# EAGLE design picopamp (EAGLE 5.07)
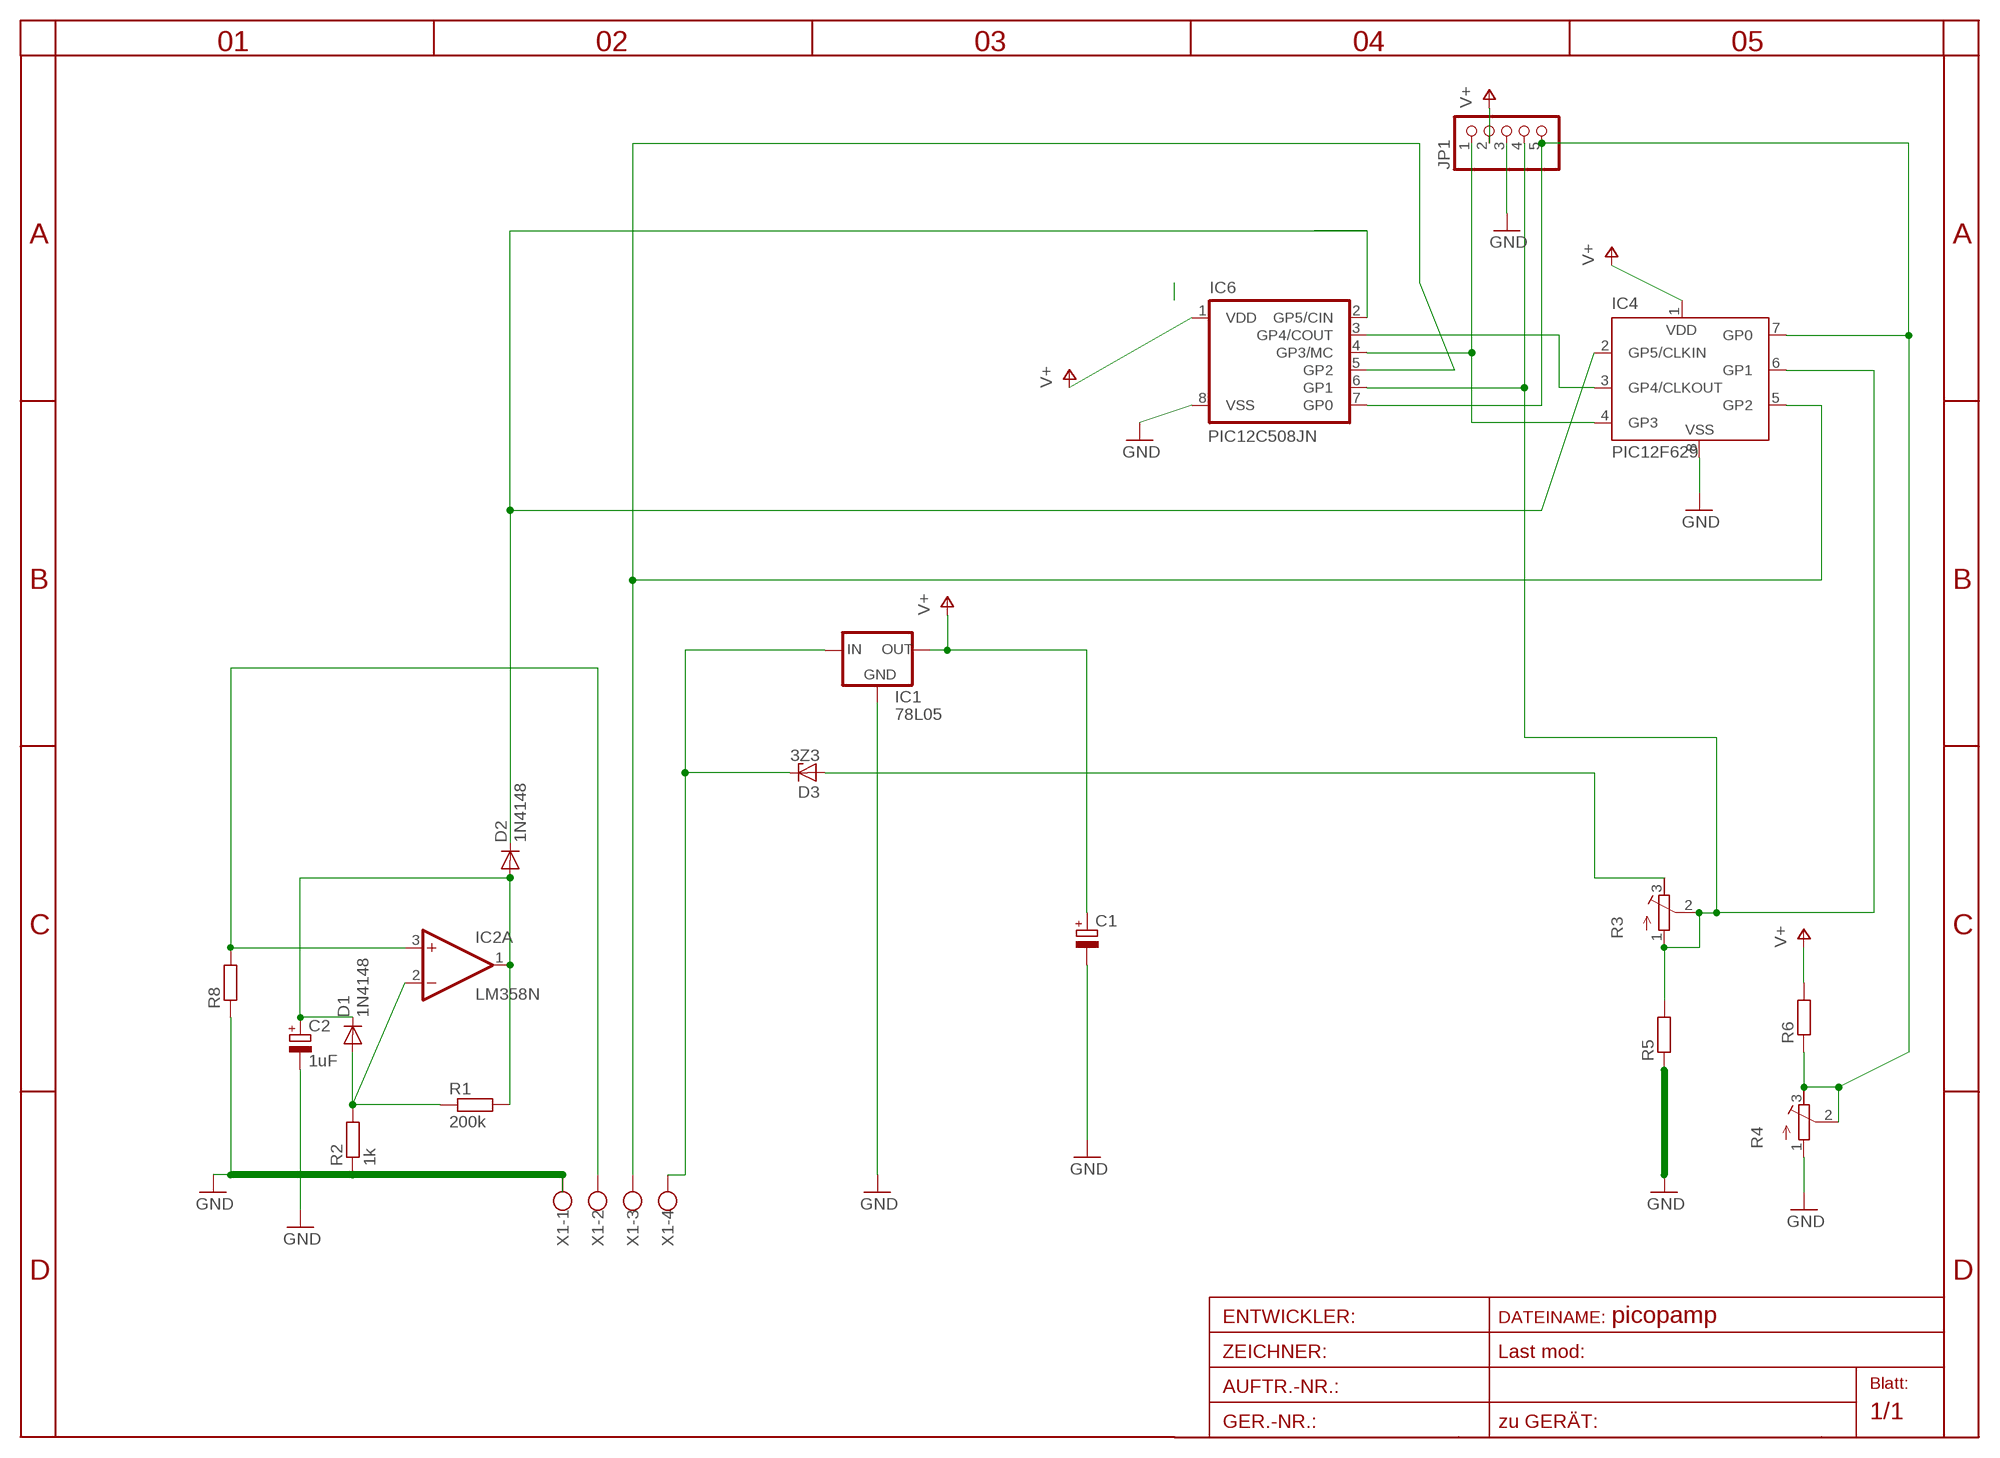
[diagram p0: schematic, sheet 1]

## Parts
C1  CPOL-EUE5-10.5  [E5-10,5]
C2  1uF  CPOL-EUE5-10.5  [E5-10,5]
D1  1N4148  [DO35-10]
D2  1N4148  [DO35-10]
D3  3Z3  1N4728  [DO41Z10]
IC1  78L05  78LXX  [78LXX]
IC2  LM358N  [DIL08]
IC4  PIC12F629  [DFN-S]
IC6  PIC12C508JN  [DIL8]
JP1  PINHD-1X5  [1X05]
R1  200k  R-EU_0207/10  [0207/10]
R2  1k  R-EU_0207/10  [0207/10]
R3  R-TRIMM3339P  [RTRIM3339P]
R4  R-TRIMM3339P  [RTRIM3339P]
R5  R-EU_0204/7  [0204/7]
R6  R-EU_0204/7  [0204/7]
R8  R-EU_0613/15  [P0613/15]
X1  W237-4  [W237-4]

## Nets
GND: C1.- C2.- IC1.GND IC4.8(VSS) IC6.8(VSS) JP1.3 R2.1 R4.1(E) R5.1 R8.1 X1.1
N$1: D2.C IC4.2(GP5/CLKIN) IC6.2(GP5/CIN)
N$2: D1.A IC2.2(A:-IN) R1.1 R2.2
N$3: D3.A R3.3(A)
N$4: IC4.6(GP1) IC6.6(GP1) JP1.4 R3.1(E) R3.2(S) R5.2
N$5: IC4.4(GP3) IC6.4(GP3/MC) JP1.1
N$6: IC4.7(GP0) IC6.7(GP0) JP1.5 R4.2(S) R4.3(A) R6.1
N$8: IC4.5(GP2) IC6.5(GP2) X1.3
N$9: IC4.3(GP4/CLKOUT) IC6.3(GP4/COUT)
N$10: IC2.3(A:+IN) R8.2 X1.2
N$12: D3.C IC1.IN X1.4
N$18: C2.+ D1.C D2.A IC2.1(A:OUT) R1.2
V+: C1.+ IC1.OUT IC4.1(VDD) IC6.1(VDD) JP1.2 R6.2
Unconnected: IC2.5(B:+IN) IC2.6(B:-IN) IC2.7(B:OUT)

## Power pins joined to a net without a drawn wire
V+: IC2.8(P:V+)
V-: IC2.4(P:V-)

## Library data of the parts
C1 C2 = rcl:CPOL-EU: POLARIZED CAPACITOR, European symbol
D1 D2 = diode:1N4148: DIODE
D3 = diode:1N4728: Z DIODE
IC1 = v-reg:78LXX: VOLTAGE REGULATOR
IC2 = linear:LM358: OP AMP also LM158; LM258; LM2904 Source: http://cache.national.com/ds/LM/LM158.pdf
IC4 = microchip:PIC12F6*: Data Sheet 8-Pin FLASH-Based 8-Bit CMOS Microcontrollers Source: http://www.microchip.com .. 41190c.pdf
IC6 = microchip:PIC12C*?: MICROCONTROLLER
JP1 = pinhead:PINHD-1X5: PIN HEADER
R1 R2 R5 R6 R8 = rcl:R-EU_: RESISTOR, European symbol
R3 R4 = rcl:R-TRIMM: Trimm resistor
X1 = con-wago-500:W237-4: WAGO SCREW CLAMP

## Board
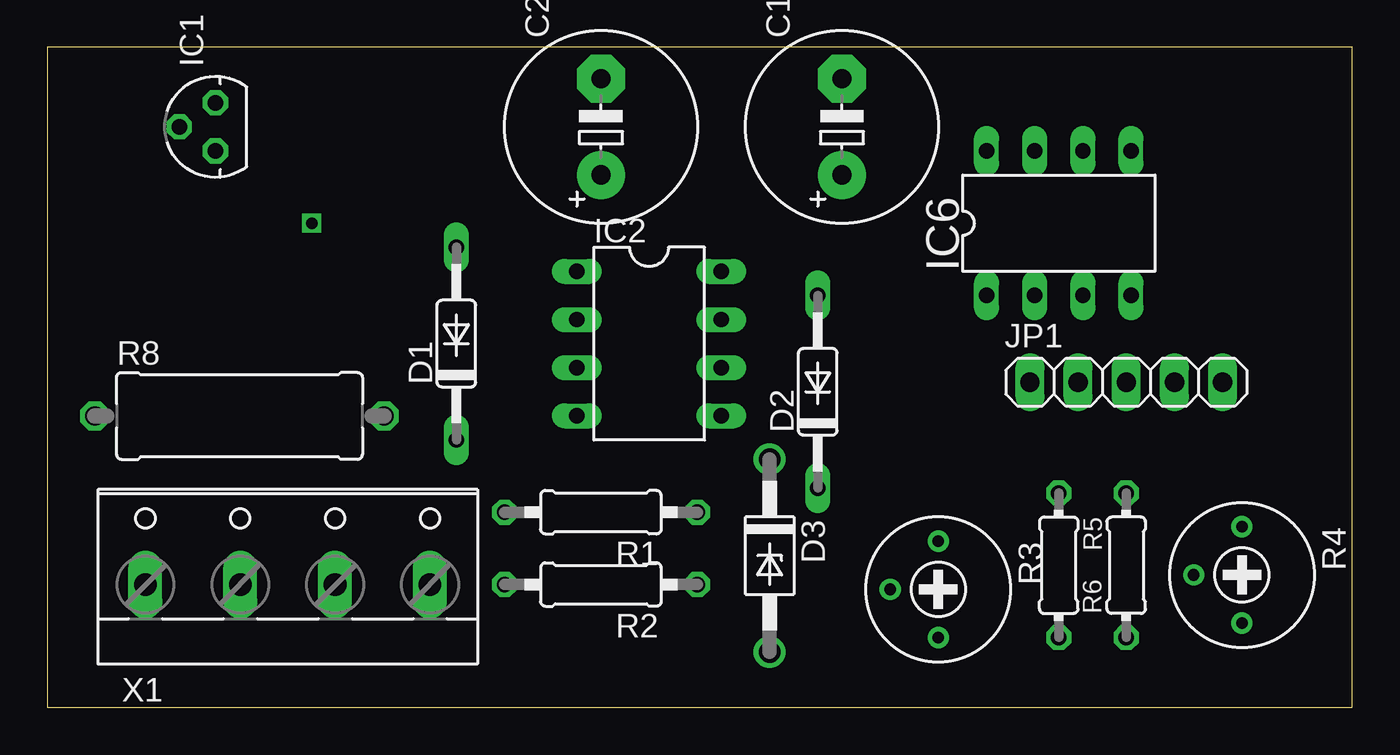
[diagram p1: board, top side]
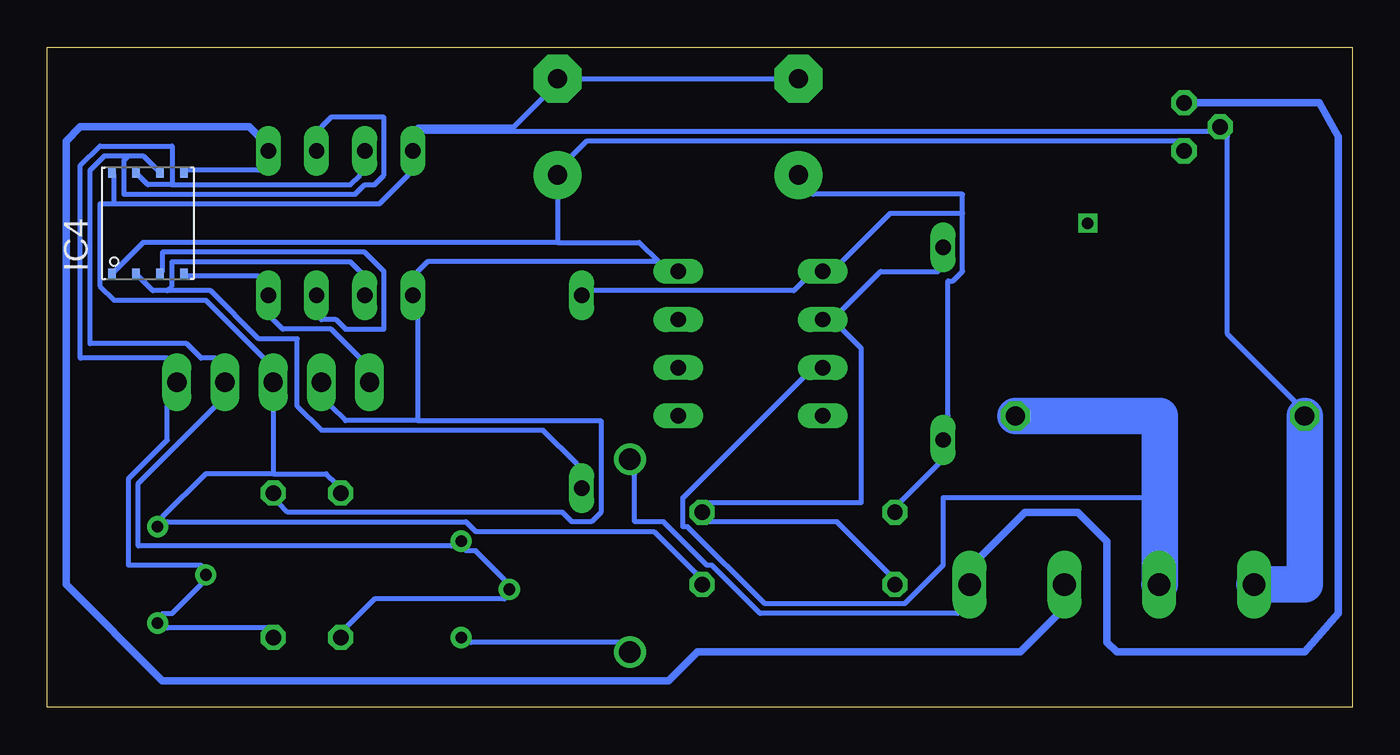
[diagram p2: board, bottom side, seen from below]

Size 68.76 x 34.79 mm. Coordinates in mm from the lower left corner, seen from the top.
Outline: 0,0 68.76,0 68.76,34.79 0,34.79 0,0
Copper layers (1*16): Top 0.035mm / dielectric 1.5mm / Bottom 0.035mm
Design rules "default": minimum track width 10mil, minimum drill 24mil, track to track 8mil, track to pad 8mil, pad to pad 8mil, via to via 8mil, smd to smd 8mil, copper to edge 40mil, drill to drill 8mil, minimum pad ring 10mil, minimum via ring 8mil, stop-mask expansion 4mil, vias tented up to drill 0mil, thermal gap 10mil
tRestrict: area 21.6,2.7 to 45.7,35.7; area 2.5,1.4 to 22.8,17.9; area 1.2,21.7 to 19,28.1; area 19,16.6 to 24.1,28.1; area 10.1,28.1 to 16.5,35.7; area 54.6,17.9 to 67.3,26.8; area 53.3,9 to 62.2,14.1; area 63.5,26.8 to 76.2,31.9; area 60.9,2.7 to 74.9,9; area 43.1,5.2 to 57.1,10.3; area 63.5,10.3 to 71.1,15.4; area 36.8,24.3 to 48.2,34.4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

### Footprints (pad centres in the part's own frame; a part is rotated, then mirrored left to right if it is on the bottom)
E5-10,5 = drill 1.016 pad 2.54 round: + -2.54,0 | drill 1.016 pad 2.54 octagon: - 2.54,0
DO35-10 = drill 0.813 long: A 5.08,0; C -5.08,0
DO41Z10 = drill 1.118 round: A 5.08,0; C -5.08,0
78LXX = drill 0.813 octagon: GND 0,1.905; IN 1.27,0; OUT -1.27,0
DIL08 = drill 0.813 long: 1 -3.81,-3.81; 2 -1.27,-3.81; 3 1.27,-3.81; 4 3.81,-3.81; 5 3.81,3.81; 6 1.27,3.81; 7 -1.27,3.81; 8 -3.81,3.81
DFN-S = smd 0.6 x 0.4: 1 -2.69,1.905; 2 -2.69,0.635; 3 -2.69,-0.635; 4 -2.69,-1.905; 5 2.69,-1.905; 6 2.69,-0.635; 7 2.69,0.635; 8 2.69,1.905
DIL8 = drill 0.813 long: 1 -3.81,-3.81; 2 -1.27,-3.81; 3 1.27,-3.81; 4 3.81,-3.81; 5 3.81,3.81; 6 1.27,3.81; 7 -1.27,3.81; 8 -3.81,3.81
1X05 = drill 1.016 long: 1 -5.08,0; 2 -2.54,0; 3 0,0; 4 2.54,0; 5 5.08,0
0207/10 = drill 0.813 octagon: 1 -5.08,0; 2 5.08,0
RTRIM3339P = drill 0.61 round: 1 -2.54,0; 2 0,-2.54; 3 2.54,0
0204/7 = drill 0.813 octagon: 1 -3.81,0; 2 3.81,0
P0613/15 = drill 1.016 octagon: 1 -7.62,0; 2 7.62,0
W237-4 = drill 1.194 long: 1 -7.5,-1.27; 2 -2.5,-1.27; 3 2.5,-1.27; 4 7.5,-1.27

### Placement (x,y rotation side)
C1  41.87,30.6 90 top
C2  29.17,30.6 90 top
D1  21.55,19.17 90 top
D2  40.6,16.63 90 top
D3  38.06,8 270 top
IC1  8.85,30.6 90 top
IC2  31.71,19.17 270 top
IC4  63.46,25.52 90 bottom
IC6  53.3,25.52 0 top
JP1  56.86,17.14 0 top
R1  29.17,10.28 180 top
R2  29.17,6.47 180 top
R3  46.95,6.22 270 top
R4  62.95,6.98 270 top
R5  53.3,7.49 270 top
R6  56.86,7.49 90 top
R8  10.12,15.36 0 top
X1  12.66,7.74 0 top

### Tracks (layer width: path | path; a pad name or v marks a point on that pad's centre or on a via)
GND
  Bottom 0.254: 56.86,12.31 54.06,12.31 53.56,11.81 R5.1 | 56.86,12.31 60.41,12.31 62.7,10.03 R4.1 62.45,9.77 46.7,9.77 46.19,9.27 36.79,9.27 34.51,6.98 R2.1 | 56.86,12.31 JP1.3 57.37,18.41 60.41,21.46 65.24,21.46 66,22.22 66,26.54 65.24,26.54 | C2.- C1.- 42.63,32.13 44.16,30.6 49.24,30.6 IC6.8 | 65.24,26.54 65.24,28.06 IC4.8 | 65.24,26.54 51.27,26.54 49.75,28.06 IC6.8 | IC6.8 48.98,30.35 7.58,30.35 IC1.GND 6.57,30.09 6.57,19.68 3.01,16.12 R8.1
  Bottom 1.93: X1.1 2.5,6.47 R8.1
N$1
  Bottom 0.254: 62.45,21.97 63.21,21.97 63.97,22.73 IC4.2 | 62.45,21.97 62.19,22.22 62.19,23.49 52.79,23.49 52.29,22.98 IC6.2 | 62.45,21.97 60.16,21.97 57.62,19.43 55.59,19.43 55.59,15.87 54.32,14.6 42.63,14.6 40.86,12.82 D2.C
N$2
  Bottom 0.254: D1.A 21.81,22.98 24.85,22.98 26.89,20.95 IC2.2 26.89,19.93 25.87,18.92 25.87,10.79 34,10.79 R1.1 34,9.77 27.14,9.77 24.35,6.98 R2.2
N$3
  Bottom 0.254: R3.3 46.44,3.42 38.57,3.42 D3.A
N$4
  Bottom 0.254: 64.48,29.08 63.72,29.08 62.95,28.32 IC4.6 | 64.48,29.08 64.73,28.82 64.73,27.05 52.54,27.05 52.03,27.55 51.52,27.55 51.02,28.06 51.02,31.11 53.81,31.11 54.32,30.6 IC6.6 | R5.2 53.05,4.19 51.52,5.71 44.67,5.71 R3.2 44.67,6.73 46.19,8.25 46.7,8.25 R3.1 47.46,8.5 63.97,8.5 63.97,11.81 59.91,15.87 JP1.4 59.91,18.41 60.67,18.41 61.43,19.17 66.51,19.17 66.51,28.32 65.75,29.08 64.48,29.08
N$5
  Bottom 0.254: IC4.4 61.43,22.73 57.62,22.73 IC6.4 56.86,20.44 56.35,19.93 53.81,19.93 52.29,18.41 JP1.1
N$6
  Bottom 0.254: 62.19,27.55 52.79,27.55 52.29,28.06 IC6.7 | 62.19,27.55 63.46,27.55 63.97,28.06 IC4.7 | R6.1 57.11,4.19 62.45,4.19 R4.3 62.7,4.95 62.19,4.95 60.67,6.47 R4.2 60.67,7.49 64.48,7.49 64.48,12.06 62.45,14.09 62.45,15.87 JP1.5 62.45,18.41 67.02,18.41 67.02,28.57 66,29.59 62.19,29.59 62.19,27.55
N$8
  Bottom 0.254: IC4.5 61.43,28.32 57.62,28.32 IC6.5
  Bottom 0.406: X1.3 15.16,5.24 17.49,2.92 34.51,2.92 36.03,1.39 62.7,1.39 67.78,6.47 67.78,29.84 67.02,30.6 58.13,30.6 57.11,29.59 IC6.5
N$9
  Bottom 0.254: IC4.3 62.7,22.98 62.7,24 52.03,24 51.02,22.98 51.02,19.93 53.05,19.93 53.56,20.44 54.32,20.44 IC6.3
N$10
  Bottom 0.254: IC2.3 28.92,17.39 35.27,11.04 35.27,9.52 35.01,9.52 30.95,5.46 23.58,5.46 21.55,7.49 21.55,11.04 10.12,11.04
  Bottom 1.93: X1.2 10.12,6.47 10.12,11.04 10.12,15.36 R8.2
N$12
  Bottom 0.254: D3.C 37.81,12.31 37.81,9.77 36.28,9.77 34,7.49 33.74,7.49 31.2,4.95 20.79,4.95 X1.4
  Bottom 0.406: X1.4 20.16,7.35 17.23,10.28 14.44,10.28 12.92,8.76 12.92,3.42 12.41,2.92 2.5,2.92 0.72,4.95 0.72,30.09 1.74,31.87 IC1.IN
N$18
  Bottom 0.254: D2.A 40.09,21.97 29.43,21.97 28.92,22.47 IC2.1 26.89,23.49 24.35,26.03 20.54,26.03 | R1.2 23.84,10.79 21.81,12.82 D1.C 21.3,15.36 21.3,22.47 21.04,22.47 20.54,22.98 20.54,26.03 | 20.54,26.03 20.54,27.05 28.41,27.05 C2.+
N$21  (via drill 0.6)
  other vias: 13.93,25.52
V+
  Bottom 0.254: IC1.OUT 9.11,29.84 40.35,29.84 41.11,29.08 C1.+ 41.87,24.51 | 49.24,15.11 53.05,15.11 53.81,15.87 JP1.2 | 49.24,15.11 39.59,15.11 39.59,10.28 40.09,9.77 41.11,9.77 41.62,10.28 56.1,10.28 56.6,10.79 R6.2 | 41.87,24.51 37.55,24.51 36.54,23.49 | 41.87,24.51 63.72,24.51 65.24,22.98 IC4.1 | 36.54,23.49 48.73,23.49 49.24,22.98 IC6.1 49.24,20.44 49.24,15.11 | 36.54,23.49 IC2.8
